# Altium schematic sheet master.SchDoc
size 279 x 215 mm; SheetNumber: 1; SheetTotal: 4
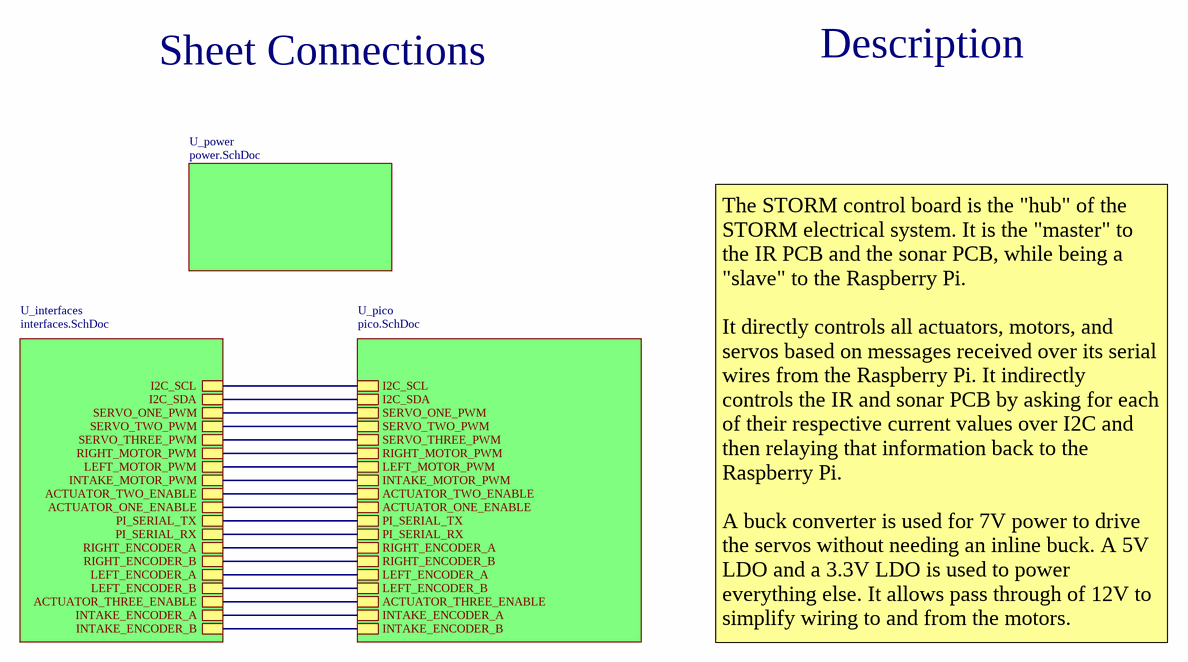
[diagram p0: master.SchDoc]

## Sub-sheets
U_interfaces = interfaces.SchDoc: I2C_SCL, I2C_SDA, SERVO_ONE_PWM, SERVO_TWO_PWM, SERVO_THREE_PWM, RIGHT_MOTOR_PWM, LEFT_MOTOR_PWM, INTAKE_MOTOR_PWM, PI_SERIAL_TX, PI_SERIAL_RX, RIGHT_ENCODER_A, RIGHT_ENCODER_B, LEFT_ENCODER_A, LEFT_ENCODER_B, ACTUATOR_TWO_ENABLE, ACTUATOR_ONE_ENABLE, ACTUATOR_THREE_ENABLE, INTAKE_ENCODER_A, INTAKE_ENCODER_B
U_pico = pico.SchDoc: LEFT_MOTOR_PWM, RIGHT_MOTOR_PWM, INTAKE_MOTOR_PWM, SERVO_ONE_PWM, SERVO_TWO_PWM, SERVO_THREE_PWM, I2C_SDA, I2C_SCL, PI_SERIAL_TX, PI_SERIAL_RX, ACTUATOR_ONE_ENABLE, ACTUATOR_TWO_ENABLE, RIGHT_ENCODER_A, RIGHT_ENCODER_B, LEFT_ENCODER_A, LEFT_ENCODER_B, ACTUATOR_THREE_ENABLE, INTAKE_ENCODER_A, INTAKE_ENCODER_B
U_power = power.SchDoc: no entries

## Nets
(unnamed): sheet U_pico/LEFT_MOTOR_PWM, sheet U_interfaces/LEFT_MOTOR_PWM
(unnamed): sheet U_pico/RIGHT_MOTOR_PWM, sheet U_interfaces/RIGHT_MOTOR_PWM  [a separate net that carries the same name]
(unnamed): sheet U_pico/INTAKE_MOTOR_PWM, sheet U_interfaces/INTAKE_MOTOR_PWM  [a separate net that carries the same name]
(unnamed): sheet U_pico/SERVO_ONE_PWM, sheet U_interfaces/SERVO_ONE_PWM  [a separate net that carries the same name]
(unnamed): sheet U_pico/SERVO_TWO_PWM, sheet U_interfaces/SERVO_TWO_PWM  [a separate net that carries the same name]
(unnamed): sheet U_pico/SERVO_THREE_PWM, sheet U_interfaces/SERVO_THREE_PWM  [a separate net that carries the same name]
(unnamed): sheet U_pico/I2C_SDA, sheet U_interfaces/I2C_SDA  [a separate net that carries the same name]
(unnamed): sheet U_pico/I2C_SCL, sheet U_interfaces/I2C_SCL  [a separate net that carries the same name]
(unnamed): sheet U_pico/PI_SERIAL_TX, sheet U_interfaces/PI_SERIAL_TX  [a separate net that carries the same name]
(unnamed): sheet U_pico/PI_SERIAL_RX, sheet U_interfaces/PI_SERIAL_RX  [a separate net that carries the same name]
(unnamed): sheet U_pico/ACTUATOR_ONE_ENABLE, sheet U_interfaces/ACTUATOR_ONE_ENABLE  [a separate net that carries the same name]
(unnamed): sheet U_pico/ACTUATOR_TWO_ENABLE, sheet U_interfaces/ACTUATOR_TWO_ENABLE  [a separate net that carries the same name]
(unnamed): sheet U_pico/RIGHT_ENCODER_A, sheet U_interfaces/RIGHT_ENCODER_A  [a separate net that carries the same name]
(unnamed): sheet U_pico/RIGHT_ENCODER_B, sheet U_interfaces/RIGHT_ENCODER_B  [a separate net that carries the same name]
(unnamed): sheet U_pico/LEFT_ENCODER_A, sheet U_interfaces/LEFT_ENCODER_A  [a separate net that carries the same name]
(unnamed): sheet U_pico/LEFT_ENCODER_B, sheet U_interfaces/LEFT_ENCODER_B  [a separate net that carries the same name]
(unnamed): sheet U_pico/ACTUATOR_THREE_ENABLE, sheet U_interfaces/ACTUATOR_THREE_ENABLE  [a separate net that carries the same name]
(unnamed): sheet U_pico/INTAKE_ENCODER_A, sheet U_interfaces/INTAKE_ENCODER_A  [a separate net that carries the same name]
(unnamed): sheet U_pico/INTAKE_ENCODER_B, sheet U_interfaces/INTAKE_ENCODER_B  [a separate net that carries the same name]

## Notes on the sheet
- Sheet Connections
- Description
- The STORM control board is the "hub" of the STORM electrical system. It is the "master" to the IR PCB and the sonar PCB, while being a "slave" to the Raspberry Pi.
  It directly controls all actuators, motors, and servos based on messages received over its serial wires from the Raspberry Pi. It indirectly controls the IR and sonar PCB by asking for each of their respective current values over I2C and then relaying that information back to the Raspberry Pi.
  A buck converter is used for 7V power to drive the servos without needing an inline buck. A 5V LDO and a 3.3V LDO is used to power everything else. It allows pass through of 12V to simplify wiring to and from the motors.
